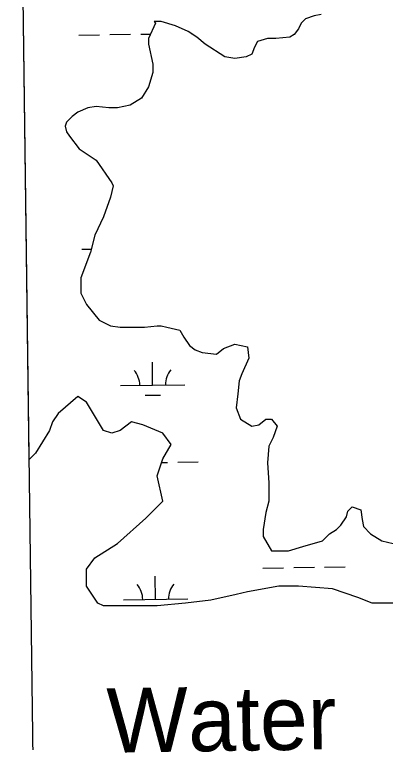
# Model space of a CAD drawing. Extents: x 3767014 to 3805179, y 361544 to 387384.
# Drawn here: x 3771133 to 3771709, y 373622 to 374752 of the extents above; entities that cross this region are included whole.
import ezdxf

# ---------------------------------------------------------------- set-up
doc = ezdxf.new("R2010")
doc.units = 0
for name, color, linetype in [('V-GRID-FRAM', 7, 'Continuous'), ('V-RIVR-IDEN', 7, 'Continuous'), ('V-TOPO-SHOR', 7, 'Continuous'), ('V-WETL-SWMP', 7, 'Continuous')]:
    doc.layers.add(name, color=color, linetype=linetype)

msp = doc.modelspace()

# ---------------------------------------------------------------- linework, layer by layer
at = {"layer": 'V-GRID-FRAM'}
msp.add_lwpolyline([(3771006.872, 385146.094), (3802799.803, 385587.734), (3803060.286, 367407.215), (3771251.489, 366965.353), (3771006.872, 385146.094)], dxfattribs=at)
at = {"layer": 'V-TOPO-SHOR'}
for p, q in [((3771584.991, 374745.803), (3771578.405, 374739.213)), ((3771598.162, 374750.196), (3771584.991, 374745.803)), ((3771609.137, 374752.392), (3771598.162, 374750.196)), ((3771352.302, 374739.213), (3771341.326, 374715.052)), ((3771361.083, 374741.41), (3771350.107, 374741.41)), ((3771350.107, 374741.41), (3771352.302, 374739.213)), ((3771383.035, 374734.82), (3771361.083, 374741.41)), ((3771402.791, 374726.034), (3771383.035, 374734.82)), ((3771578.405, 374739.213), (3771574.015, 374730.427)), ((3771415.962, 374717.248), (3771402.791, 374726.034)), ((3771567.429, 374721.641), (3771560.844, 374717.248)), ((3771574.015, 374730.427), (3771567.429, 374721.641)), ((3771341.326, 374715.052), (3771341.326, 374706.266)), ((3771429.133, 374706.266), (3771415.962, 374717.248)), ((3771510.355, 374710.659), (3771505.964, 374701.873)), ((3771525.721, 374715.052), (3771510.355, 374710.659)), ((3771538.892, 374715.052), (3771525.721, 374715.052)), ((3771560.844, 374717.248), (3771538.892, 374715.052)), ((3771341.326, 374706.266), (3771347.912, 374675.515)), ((3771459.866, 374686.497), (3771429.133, 374706.266)), ((3771505.964, 374701.873), (3771501.574, 374690.89)), ((3771475.232, 374684.301), (3771459.866, 374686.497)), ((3771492.793, 374686.497), (3771475.232, 374684.301)), ((3771501.574, 374690.89), (3771492.793, 374686.497)), ((3771347.912, 374675.515), (3771347.912, 374662.336)), ((3771347.912, 374662.336), (3771341.326, 374640.371)), ((3771341.326, 374640.371), (3771330.35, 374622.799)), ((3771330.35, 374622.799), (3771312.789, 374611.817)), ((3771246.934, 374607.424), (3771231.568, 374600.834)), ((3771260.105, 374609.62), (3771246.934, 374607.424)), ((3771279.861, 374607.424), (3771260.105, 374609.62)), ((3771293.032, 374607.424), (3771279.861, 374607.424)), ((3771312.789, 374611.817), (3771293.032, 374607.424)), ((3771231.568, 374600.834), (3771222.787, 374594.245)), ((3771214.006, 374585.459), (3771211.811, 374578.869)), ((3771222.787, 374594.245), (3771214.006, 374585.459)), ((3771211.811, 374578.869), (3771214.006, 374570.084)), ((3771214.006, 374570.084), (3771218.397, 374563.494)), ((3771218.397, 374563.494), (3771233.763, 374543.726)), ((3771233.763, 374543.726), (3771260.105, 374526.154)), ((3771260.105, 374526.154), (3771284.252, 374491.01)), ((3771286.447, 374486.617), (3771282.057, 374469.045)), ((3771284.252, 374491.01), (3771286.447, 374486.617)), ((3771282.057, 374469.045), (3771271.081, 374438.294)), ((3771271.081, 374438.294), (3771257.91, 374409.74)), ((3771257.91, 374409.74), (3771251.324, 374383.382)), ((3771251.324, 374383.382), (3771235.958, 374343.845)), ((3771235.958, 374343.845), (3771235.958, 374319.684)), ((3771235.958, 374319.684), (3771244.739, 374302.112)), ((3771244.739, 374302.112), (3771264.495, 374277.95)), ((3771264.495, 374277.95), (3771282.057, 374269.164)), ((3771282.057, 374269.164), (3771297.423, 374266.968)), ((3771334.741, 374266.968), (3771354.497, 374269.164)), ((3771354.497, 374269.164), (3771361.083, 374269.164)), ((3771361.083, 374269.164), (3771369.864, 374266.968)), ((3771297.423, 374266.968), (3771334.741, 374266.968)), ((3771369.864, 374266.968), (3771389.62, 374262.575)), ((3771389.62, 374262.575), (3771396.206, 374251.592)), ((3771396.206, 374251.592), (3771404.986, 374238.414)), ((3771404.986, 374238.414), (3771413.767, 374231.824)), ((3771446.695, 374225.235), (3771457.67, 374234.021)), ((3771457.67, 374234.021), (3771475.232, 374240.61)), ((3771475.232, 374240.61), (3771494.988, 374236.217)), ((3771494.988, 374236.217), (3771497.184, 374218.645)), ((3771413.767, 374231.824), (3771424.743, 374227.431)), ((3771424.743, 374227.431), (3771446.695, 374225.235)), ((3771497.184, 374218.645), (3771486.208, 374194.484)), ((3771486.208, 374194.484), (3771481.817, 374183.501)), ((3771481.817, 374183.501), (3771479.622, 374163.733)), ((3771231.567, 374159.34), (3771200.835, 374132.982)), ((3771244.738, 374150.554), (3771231.567, 374159.34)), ((3771479.622, 374163.733), (3771477.427, 374141.768)), ((3771271.08, 374106.624), (3771244.738, 374150.554)), ((3771200.835, 374132.982), (3771192.054, 374119.803)), ((3771477.427, 374141.768), (3771484.013, 374124.196)), ((3771484.013, 374124.196), (3771501.574, 374113.214)), ((3771512.55, 374115.41), (3771523.526, 374124.196)), ((3771523.526, 374124.196), (3771532.306, 374124.196)), ((3771532.306, 374124.196), (3771541.087, 374113.214)), ((3771192.054, 374119.803), (3771187.664, 374106.624)), ((3771314.984, 374119.803), (3771297.422, 374106.624)), ((3771332.545, 374115.41), (3771314.984, 374119.803)), ((3771363.278, 374102.231), (3771332.545, 374115.41)), ((3771501.574, 374113.214), (3771512.55, 374115.41)), ((3771541.087, 374113.214), (3771534.502, 374095.642)), ((3771187.664, 374106.624), (3771165.712, 374071.48)), ((3771284.251, 374102.231), (3771271.08, 374106.624)), ((3771297.422, 374106.624), (3771284.251, 374102.231)), ((3771376.449, 374084.659), (3771363.278, 374102.231)), ((3771534.502, 374095.642), (3771527.916, 374082.463)), ((3771363.278, 374062.694), (3771376.449, 374084.659)), ((3771527.916, 374082.463), (3771525.721, 374056.105)), ((3771165.712, 374071.48), (3771156.009, 374061.771)), ((3771354.497, 374036.337), (3771363.278, 374062.694)), ((3771525.721, 374056.105), (3771527.916, 374025.354)), ((3771363.278, 373996.8), (3771354.497, 374036.337)), ((3771527.916, 374025.354), (3771527.916, 373996.8)), ((3771336.935, 373970.442), (3771363.278, 373996.8)), ((3771527.916, 373996.8), (3771523.526, 373979.228)), ((3771650.846, 373981.425), (3771657.432, 373988.014)), ((3771657.432, 373988.014), (3771670.603, 373983.621)), ((3771523.526, 373979.228), (3771519.135, 373952.87)), ((3771648.651, 373972.639), (3771650.846, 373981.425)), ((3771670.603, 373983.621), (3771672.798, 373968.246)), ((3771293.032, 373930.905), (3771336.935, 373970.442)), ((3771639.87, 373959.46), (3771648.651, 373972.639)), ((3771672.798, 373968.246), (3771674.993, 373957.263)), ((3771519.135, 373952.87), (3771519.135, 373941.887)), ((3771622.309, 373946.281), (3771633.285, 373952.87)), ((3771633.285, 373952.87), (3771639.87, 373959.46)), ((3771674.993, 373957.263), (3771685.969, 373946.281)), ((3771519.135, 373941.887), (3771532.306, 373919.922)), ((3771611.333, 373935.298), (3771622.309, 373946.281)), ((3771685.969, 373946.281), (3771703.53, 373935.298)), ((3771257.909, 373908.94), (3771293.032, 373930.905)), ((3771580.601, 373926.512), (3771611.333, 373935.298)), ((3771703.53, 373935.298), (3771721.092, 373930.905)), ((3771532.306, 373919.922), (3771558.649, 373919.923)), ((3771558.649, 373919.923), (3771580.601, 373926.512)), ((3771244.738, 373891.368), (3771257.909, 373908.94)), ((3771244.738, 373865.01), (3771244.738, 373891.368)), ((3771262.3, 373838.652), (3771244.738, 373865.01)), ((3771543.282, 373865.01), (3771494.988, 373856.224)), ((3771574.014, 373865.01), (3771543.282, 373865.01)), ((3771626.698, 373860.617), (3771574.014, 373865.01)), ((3771477.427, 373851.831), (3771437.913, 373843.045)), ((3771494.988, 373856.224), (3771477.427, 373851.831)), ((3771666.211, 373847.438), (3771626.698, 373860.617)), ((3771271.08, 373834.259), (3771262.3, 373838.652)), ((3771398.4, 373838.652), (3771354.497, 373834.259)), ((3771437.913, 373843.045), (3771398.4, 373838.652)), ((3771688.163, 373838.652), (3771666.211, 373847.438)), ((3771736.457, 373838.652), (3771688.163, 373838.652)), ((3771354.497, 373834.259), (3771271.08, 373834.259))]:
    msp.add_line(p, q, dxfattribs=at)
at = {"layer": 'V-WETL-SWMP'}
for p, q in [((3771156.009, 374061.771), (3771141.312, 375154.034)), ((3771584.991, 374745.803), (3771578.405, 374739.213)), ((3771598.162, 374750.196), (3771584.991, 374745.803)), ((3771609.137, 374752.392), (3771598.162, 374750.196)), ((3771352.302, 374739.213), (3771341.326, 374715.052)), ((3771361.083, 374741.41), (3771350.107, 374741.41)), ((3771350.107, 374741.41), (3771352.302, 374739.213)), ((3771383.035, 374734.82), (3771361.083, 374741.41)), ((3771402.791, 374726.034), (3771383.035, 374734.82)), ((3771578.405, 374739.213), (3771574.015, 374730.427)), ((3771233.241, 374720.611), (3771265.237, 374721.055)), ((3771281.236, 374721.277), (3771313.233, 374721.722)), ((3771329.231, 374721.944), (3771344.554, 374722.157)), ((3771415.962, 374717.248), (3771402.791, 374726.034)), ((3771407.297, 374723.028), (3771409.224, 374723.055)), ((3771567.429, 374721.641), (3771560.844, 374717.248)), ((3771574.015, 374730.427), (3771567.429, 374721.641)), ((3771341.326, 374715.052), (3771341.326, 374706.266)), ((3771429.133, 374706.266), (3771415.962, 374717.248)), ((3771510.355, 374710.659), (3771505.964, 374701.873)), ((3771525.721, 374715.052), (3771510.355, 374710.659)), ((3771538.892, 374715.052), (3771525.721, 374715.052)), ((3771560.844, 374717.248), (3771538.892, 374715.052)), ((3771341.326, 374706.266), (3771347.912, 374675.515)), ((3771459.866, 374686.497), (3771429.133, 374706.266)), ((3771505.964, 374701.873), (3771501.574, 374690.89)), ((3771475.232, 374684.301), (3771459.866, 374686.497)), ((3771492.793, 374686.497), (3771475.232, 374684.301)), ((3771501.574, 374690.89), (3771492.793, 374686.497)), ((3771347.912, 374675.515), (3771347.912, 374662.336)), ((3771347.912, 374662.336), (3771341.326, 374640.371)), ((3771341.326, 374640.371), (3771330.35, 374622.799)), ((3771330.35, 374622.799), (3771312.789, 374611.817)), ((3771246.934, 374607.424), (3771231.568, 374600.834)), ((3771260.105, 374609.62), (3771246.934, 374607.424)), ((3771279.861, 374607.424), (3771260.105, 374609.62)), ((3771293.032, 374607.424), (3771279.861, 374607.424)), ((3771312.789, 374611.817), (3771293.032, 374607.424)), ((3771231.568, 374600.834), (3771222.787, 374594.245)), ((3771214.006, 374585.459), (3771211.811, 374578.869)), ((3771222.787, 374594.245), (3771214.006, 374585.459)), ((3771211.811, 374578.869), (3771214.006, 374570.084)), ((3771214.006, 374570.084), (3771218.397, 374563.494)), ((3771218.397, 374563.494), (3771233.763, 374543.726)), ((3771233.763, 374543.726), (3771260.105, 374526.154)), ((3771260.105, 374526.154), (3771284.252, 374491.01)), ((3771286.447, 374486.617), (3771282.057, 374469.045)), ((3771284.252, 374491.01), (3771286.447, 374486.617)), ((3771282.057, 374469.045), (3771271.081, 374438.294)), ((3771271.081, 374438.294), (3771257.91, 374409.74)), ((3771257.91, 374409.74), (3771251.324, 374383.382)), ((3771251.324, 374383.382), (3771235.958, 374343.845)), ((3771237.861, 374387.968), (3771252.521, 374388.171)), ((3771235.958, 374343.845), (3771235.958, 374319.684)), ((3771235.958, 374319.684), (3771244.739, 374302.112)), ((3771244.739, 374302.112), (3771264.495, 374277.95)), ((3771264.495, 374277.95), (3771282.057, 374269.164)), ((3771282.057, 374269.164), (3771297.423, 374266.968)), ((3771334.741, 374266.968), (3771354.497, 374269.164)), ((3771354.497, 374269.164), (3771361.083, 374269.164)), ((3771361.083, 374269.164), (3771369.864, 374266.968)), ((3771297.423, 374266.968), (3771334.741, 374266.968)), ((3771369.864, 374266.968), (3771389.62, 374262.575)), ((3771389.62, 374262.575), (3771396.206, 374251.592)), ((3771396.206, 374251.592), (3771404.986, 374238.414)), ((3771404.986, 374238.414), (3771413.767, 374231.824)), ((3771446.695, 374225.235), (3771457.67, 374234.021)), ((3771457.67, 374234.021), (3771475.232, 374240.61)), ((3771475.232, 374240.61), (3771494.988, 374236.217)), ((3771494.988, 374236.217), (3771497.184, 374218.645)), ((3771413.767, 374231.824), (3771424.743, 374227.431)), ((3771424.743, 374227.431), (3771446.695, 374225.235)), ((3771347.648, 374176.868), (3771347.148, 374212.865)), ((3771497.184, 374218.645), (3771486.208, 374194.484)), ((3771486.208, 374194.484), (3771481.817, 374183.501)), ((3771297.653, 374176.174), (3771397.643, 374177.563)), ((3771481.817, 374183.501), (3771479.622, 374163.733)), ((3771231.567, 374159.34), (3771200.835, 374132.982)), ((3771244.738, 374150.554), (3771231.567, 374159.34)), ((3771335.864, 374161.272), (3771359.861, 374161.605)), ((3771479.622, 374163.733), (3771477.427, 374141.768)), ((3771271.08, 374106.624), (3771244.738, 374150.554)), ((3771200.835, 374132.982), (3771192.054, 374119.803)), ((3771477.427, 374141.768), (3771484.013, 374124.196)), ((3771484.013, 374124.196), (3771501.574, 374113.214)), ((3771512.55, 374115.41), (3771523.526, 374124.196)), ((3771523.526, 374124.196), (3771532.306, 374124.196)), ((3771532.306, 374124.196), (3771541.087, 374113.214)), ((3771192.054, 374119.803), (3771187.664, 374106.624)), ((3771314.984, 374119.803), (3771297.422, 374106.624)), ((3771332.545, 374115.41), (3771314.984, 374119.803)), ((3771363.278, 374102.231), (3771332.545, 374115.41)), ((3771501.574, 374113.214), (3771512.55, 374115.41)), ((3771541.087, 374113.214), (3771534.502, 374095.642)), ((3771187.664, 374106.624), (3771165.712, 374071.48)), ((3771284.251, 374102.231), (3771271.08, 374106.624)), ((3771297.422, 374106.624), (3771284.251, 374102.231)), ((3771376.449, 374084.659), (3771363.278, 374102.231)), ((3771534.502, 374095.642), (3771527.916, 374082.463)), ((3771363.278, 374062.694), (3771376.449, 374084.659)), ((3771527.916, 374082.463), (3771525.721, 374056.105)), ((3771165.712, 374071.48), (3771156.009, 374061.771)), ((3771354.497, 374036.337), (3771363.278, 374062.694)), ((3771361.373, 374056.976), (3771370.47, 374057.103)), ((3771386.468, 374057.325), (3771418.465, 374057.769)), ((3771525.721, 374056.105), (3771527.916, 374025.354)), ((3771363.278, 373996.8), (3771354.497, 374036.337)), ((3771527.916, 374025.354), (3771527.916, 373996.8)), ((3771336.935, 373970.442), (3771363.278, 373996.8)), ((3771527.916, 373996.8), (3771523.526, 373979.228)), ((3771650.846, 373981.425), (3771657.432, 373988.014)), ((3771657.432, 373988.014), (3771670.603, 373983.621)), ((3771523.526, 373979.228), (3771519.135, 373952.87)), ((3771648.651, 373972.639), (3771650.846, 373981.425)), ((3771670.603, 373983.621), (3771672.798, 373968.246)), ((3771293.032, 373930.905), (3771336.935, 373970.442)), ((3771639.87, 373959.46), (3771648.651, 373972.639)), ((3771672.798, 373968.246), (3771674.993, 373957.263)), ((3771519.135, 373952.87), (3771519.135, 373941.887)), ((3771622.309, 373946.281), (3771633.285, 373952.87)), ((3771633.285, 373952.87), (3771639.87, 373959.46)), ((3771674.993, 373957.263), (3771685.969, 373946.281)), ((3771519.135, 373941.887), (3771532.306, 373919.922)), ((3771611.333, 373935.298), (3771622.309, 373946.281)), ((3771685.969, 373946.281), (3771703.53, 373935.298)), ((3771257.909, 373908.94), (3771293.032, 373930.905)), ((3771580.601, 373926.512), (3771611.333, 373935.298)), ((3771703.53, 373935.298), (3771721.092, 373930.905)), ((3771532.306, 373919.922), (3771558.649, 373919.923)), ((3771558.649, 373919.923), (3771580.601, 373926.512)), ((3771244.738, 373891.368), (3771257.909, 373908.94)), ((3771244.738, 373865.01), (3771244.738, 373891.368)), ((3771518.672, 373892.971), (3771550.669, 373893.416)), ((3771566.667, 373893.638), (3771598.664, 373894.083)), ((3771614.663, 373894.305), (3771646.66, 373894.749)), ((3771352.269, 373844.225), (3771351.769, 373880.222)), ((3771262.3, 373838.652), (3771244.738, 373865.01)), ((3771543.282, 373865.01), (3771494.988, 373856.224)), ((3771574.014, 373865.01), (3771543.282, 373865.01)), ((3771626.698, 373860.617), (3771574.014, 373865.01)), ((3771477.427, 373851.831), (3771437.913, 373843.045)), ((3771494.988, 373856.224), (3771477.427, 373851.831)), ((3771666.211, 373847.438), (3771626.698, 373860.617)), ((3771271.08, 373834.259), (3771262.3, 373838.652)), ((3771302.274, 373843.531), (3771402.264, 373844.92)), ((3771398.4, 373838.652), (3771354.497, 373834.259)), ((3771437.913, 373843.045), (3771398.4, 373838.652)), ((3771688.163, 373838.652), (3771666.211, 373847.438)), ((3771736.457, 373838.652), (3771688.163, 373838.652)), ((3771354.497, 373834.259), (3771271.08, 373834.259))]:
    msp.add_line(p, q, dxfattribs=at)
for centre, start, end in [((3771402.879, 374178.11), 140.024034, 181.567693), ((3771292.404, 374176.576), 0.024037, 41.567696), ((3771297.025, 373843.933), 0.024037, 41.567696), ((3771407.5, 373845.467), 140.024034, 181.567693)]:
    msp.add_arc(centre, 35.246, start, end, dxfattribs=at)

# ---------------------------------------------------------------- texts
at = {"layer": 'V-RIVR-IDEN'}
msp.add_text('Water', height=100, rotation=0.919589, dxfattribs=at).set_placement((3771277.061, 373606.074))

doc.saveas('drawing.dxf')
